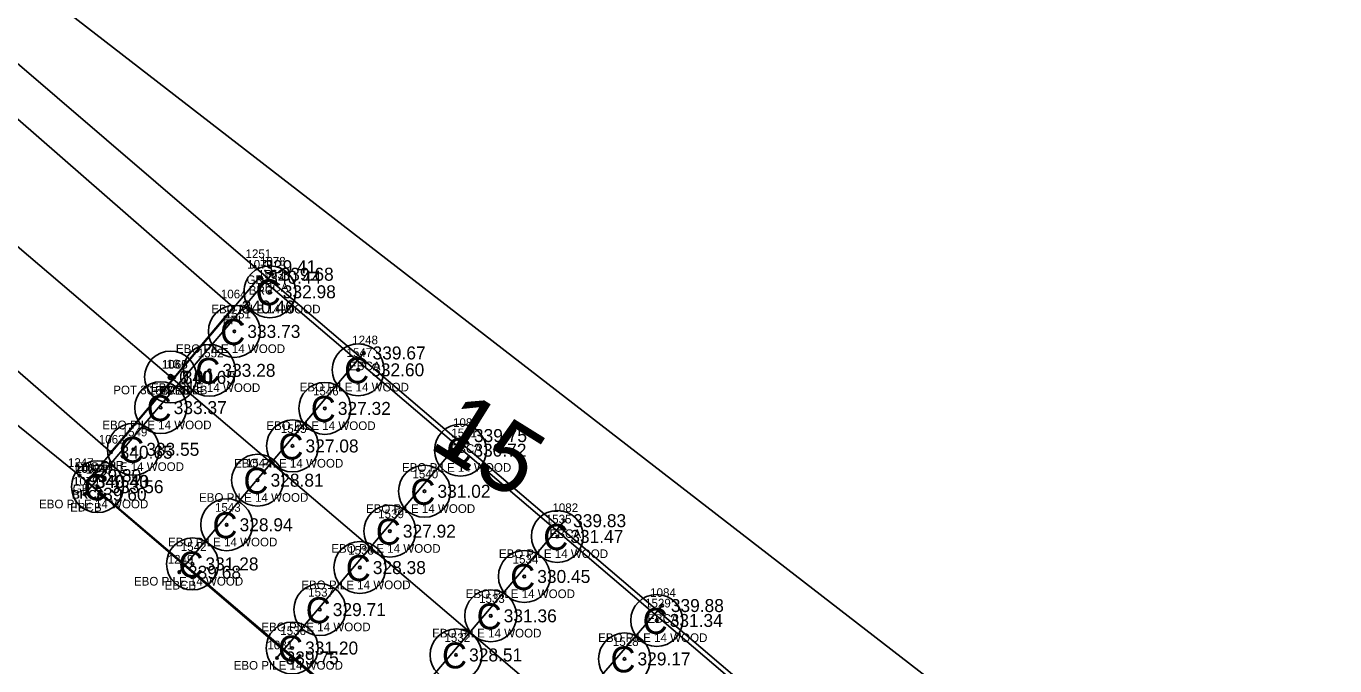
# Model space of a CAD drawing. Extents: x 2006517 to 2008868, y 1001613 to 1004633.
# Drawn here: x 2007680.3 to 2007831.6, y 1003041.7 to 1003115.7 of the extents above; entities that cross this region are included whole.
import ezdxf

# ---------------------------------------------------------------- set-up
doc = ezdxf.new("R2010")
doc.units = 0
for name, color, linetype in [('RD_EX_Bridge', 7, 'Continuous'), ('RD_EX_Bridge_txCode', 7, 'Continuous'), ('RD_EX_GuardRail', 7, 'Continuous'), ('RD_EX_GuardRail_txCode', 7, 'Continuous'), ('RD_EX_Road', 7, 'Continuous'), ('RD_EX_Road_txCode', 7, 'Continuous'), ('RD_EX_TX_Bridge_ELEV', 7, 'Continuous'), ('RD_EX_TX_GuardRail_ELEV', 7, 'Continuous'), ('RD_EX_TX_Road_ELEV', 7, 'Continuous'), ('RD_EX_VEG', 7, 'Continuous'), ('RD_HC_Cl', 7, 'Continuous'), ('RD_HC_Data', 7, 'Continuous'), ('RD_HC_Survey_ELEV', 7, 'Continuous'), ('RD_HC_TX_Sta50', 7, 'Continuous'), ('RD_HC_txCode', 7, 'Continuous'), ('RD_SMD_Locator', 7, 'Continuous')]:
    doc.layers.add(name, color=color, linetype=linetype)

msp = doc.modelspace()

# ---------------------------------------------------------------- linework, layer by layer
at = {"layer": 'RD_EX_Bridge'}
for p, q in [((2007708.71, 1003087), (2007687.08, 1003061.57)), ((2007719.34, 1003077.9), (2007698, 1003052.55)), ((2007731.06, 1003068.35), (2007709.29, 1003042.64)), ((2007742.52, 1003058.51), (2007720.73, 1003032.86)), ((2007753.82, 1003048.7), (2007731.73, 1003023.29))]:
    msp.add_line(p, q, dxfattribs=at)
msp.add_lwpolyline([(2007687.31, 1003063.05), (2007707.28, 1003086.65), (2007780.18, 1003024.5), (2007853.73, 1002962.01), (2007935.92, 1002891.93), (2007915.63, 1002868.5), (2007835.4, 1002936.88), (2007761.92, 1002999.52), (2007687.36, 1003063.04)], dxfattribs=at)
for centre in [(2007708.46, 1003084.97), (2007704.36, 1003080.39), (2007701.48, 1003075.89), (2007718.68, 1003075.95), (2007695.85, 1003071.58), (2007714.82, 1003071.49), (2007692.68, 1003066.76), (2007711.09, 1003067.15), (2007730.5, 1003066.66), (2007688.54, 1003062.44), (2007707.05, 1003063.19), (2007726.34, 1003061.91), (2007703.47, 1003058.04), (2007722.34, 1003057.3), (2007741.7, 1003056.69), (2007699.52, 1003053.51), (2007718.87, 1003053.09), (2007737.88, 1003052.06), (2007714.24, 1003048.23), (2007734, 1003047.51), (2007753.19, 1003046.98), (2007711.04, 1003043.79), (2007729.99, 1003042.99), (2007749.47, 1003042.53)]:
    msp.add_circle(centre, 3, dxfattribs=at)
at = {"layer": 'RD_EX_GuardRail'}
for points in [[(2007643.64, 1003141.95), (2007706.71, 1003087.87), (2007781.32, 1003024.2), (2007854.58, 1002961.97), (2007936.8, 1002891.67), (2008015.14, 1002821.85)], [(2007623.33, 1003114.9), (2007686.46, 1003063.73), (2007759.92, 1003000.81), (2007833.42, 1002938.17), (2007916.12, 1002867.57), (2007997.28, 1002798.14)]]:
    msp.add_lwpolyline(points, dxfattribs=at)
at = {"layer": 'RD_EX_Road'}
for points in [[(2007106.91, 1004392.51), (2007131.76, 1004296.89), (2007157.25, 1004199.89), (2007181.73, 1004104.01), (2007207.15, 1004006.25), (2007232.28, 1003909.68), (2007245.22, 1003859.08), (2007256.72, 1003814.23), (2007281.54, 1003717.98), (2007306.68, 1003621.16), (2007321.26, 1003569.47), (2007336.92, 1003524.18), (2007356.72, 1003477.39), (2007378.16, 1003434.29), (2007403.27, 1003391.08), (2007429.97, 1003350.71), (2007461.24, 1003310.36), (2007493.28, 1003274.3), (2007528.72, 1003239.05), (2007564.79, 1003204.88), (2007704.21, 1003083.21), (2007697.4, 1003075.08)], [(2007086.98, 1004389.35), (2007112.54, 1004291.29), (2007137.93, 1004194.16), (2007162.5, 1004098.34), (2007187.86, 1004000.45), (2007213, 1003903.71), (2007225.92, 1003855.13), (2007237.94, 1003808.26), (2007262.59, 1003712.12), (2007287.86, 1003616), (2007302.39, 1003563.75), (2007318.2, 1003517.19), (2007334.44, 1003476.78), (2007338.05, 1003468.98), (2007341.25, 1003461.96), (2007359.99, 1003424.53), (2007383.83, 1003381.83), (2007412.14, 1003338.08), (2007443.3, 1003296.86), (2007477.49, 1003258.92), (2007512.95, 1003223.51), (2007550.46, 1003188.01), (2007690.1, 1003066.42), (2007697.4, 1003075.08)]]:
    msp.add_lwpolyline(points, dxfattribs=at)
at = {"layer": 'RD_EX_VEG'}
msp.add_lwpolyline([(2007473.93, 1003322.69), (2007503.07, 1003282.99), (2007540.25, 1003252.05), (2007579.27, 1003219.13), (2007642.18, 1003150.48), (2007952.5, 1002910.4), (2008017.59, 1002836.73), (2008047.98, 1002799.05), (2008087.42, 1002767.09), (2008121.48, 1002729.06), (2008151.49, 1002690.42), (2008185.86, 1002650.76), (2008208.76, 1002609.15), (2008254.04, 1002533.01), (2008311.38, 1002450.28), (2008360.35, 1002372.97), (2008409.06, 1002292.02), (2008460.63, 1002215.28), (2008512.48, 1002133.62), (2008564.88, 1002053.16), (2008614.62, 1001980.71), (2008661.43, 1001938.2)], dxfattribs=at)
at = {"layer": 'RD_HC_Cl'}
msp.add_line((2007559.77, 1003192.01), (2007994.36, 1002821.78), dxfattribs=at)
at = {"layer": 'RD_HC_Data'}
for radius in [3, 0.282]:
    msp.add_circle((2007696.99, 1003075.12), radius, dxfattribs=at)
at = {"layer": 'RD_SMD_Locator'}
for centre in [(2007706.71, 1003087.87), (2007707.28, 1003086.65), (2007708.71, 1003087), (2007708.46, 1003084.97), (2007704.21, 1003083.21), (2007704.36, 1003080.39), (2007719.34, 1003077.9), (2007701.48, 1003075.89), (2007718.68, 1003075.95), (2007696.99, 1003075.12), (2007697.4, 1003075.08), (2007697.4, 1003075.08), (2007695.85, 1003071.58), (2007714.82, 1003071.49), (2007731.06, 1003068.35), (2007690.1, 1003066.42), (2007692.68, 1003066.76), (2007711.09, 1003067.15), (2007730.5, 1003066.66), (2007686.46, 1003063.73), (2007707.05, 1003063.19), (2007687.31, 1003063.05), (2007687.36, 1003063.04), (2007688.54, 1003062.44), (2007726.34, 1003061.91), (2007687.08, 1003061.57), (2007703.47, 1003058.04), (2007722.34, 1003057.3), (2007742.52, 1003058.51), (2007741.7, 1003056.69), (2007699.52, 1003053.51), (2007718.87, 1003053.09), (2007698, 1003052.55), (2007737.88, 1003052.06), (2007714.24, 1003048.23), (2007753.82, 1003048.7), (2007734, 1003047.51), (2007753.19, 1003046.98), (2007711.04, 1003043.79), (2007709.29, 1003042.64), (2007729.99, 1003042.99), (2007749.47, 1003042.53)]:
    msp.add_circle(centre, 0.15, dxfattribs=at)

# ---------------------------------------------------------------- texts
at = {"layer": 'RD_EX_Bridge'}
for p in [(2007706.83, 1003083.41), (2007702.73, 1003078.83), (2007699.85, 1003074.33), (2007717.05, 1003074.39), (2007694.22, 1003070.02), (2007713.19, 1003069.93), (2007691.05, 1003065.2), (2007709.46, 1003065.59), (2007728.87, 1003065.09), (2007686.91, 1003060.87), (2007705.41, 1003061.63), (2007724.71, 1003060.35), (2007701.83, 1003056.48), (2007720.71, 1003055.74), (2007740.07, 1003055.13), (2007697.89, 1003051.95), (2007717.24, 1003051.53), (2007736.25, 1003050.5), (2007712.61, 1003046.66), (2007732.37, 1003045.95), (2007751.56, 1003045.42), (2007709.41, 1003042.23), (2007728.36, 1003041.43), (2007747.84, 1003040.97)]:
    msp.add_text('C', height=3, dxfattribs=at).set_placement(p)
at = {"layer": 'RD_EX_Bridge_txCode'}
for s, p in [('1070', (2007705.85, 1003087.65)), ('1078', (2007707.32, 1003088)), ('EBCA', (2007706.99, 1003085)), ('1553', (2007707.11, 1003086.47)), ('BRC', (2007706.03, 1003084.65)), ('EBO PILE 14 WOOD', (2007701.69, 1003082.47)), ('1551', (2007703.3, 1003081.89)), ('EBO PILE 14 WOOD', (2007697.6, 1003077.89)), ('1547', (2007717.33, 1003077.45)), ('1248', (2007717.99, 1003078.9)), ('1552', (2007700.13, 1003077.39)), ('EBCA', (2007717.62, 1003075.9)), ('1550', (2007694.47, 1003073.08)), ('EBO PILE 14 WOOD', (2007694.72, 1003073.39)), ('EBO PILE 14 WOOD', (2007711.91, 1003073.45)), ('1546', (2007713.45, 1003072.99)), ('EBO PILE 14 WOOD', (2007689.09, 1003069.08)), ('EBO PILE 14 WOOD', (2007708.06, 1003068.99)), ('1545', (2007709.74, 1003068.65)), ('1080', (2007729.64, 1003069.35)), ('1549', (2007691.33, 1003068.26)), ('1541', (2007729.44, 1003068.16)), ('EBCA', (2007729.35, 1003066.35)), ('1069', (2007685.9, 1003064.05)), ('EBO PILE 14 WOOD', (2007685.91, 1003064.26)), ('1077', (2007685.98, 1003064.04)), ('1548', (2007687.2, 1003063.94)), ('EBO PILE 14 WOOD', (2007704.32, 1003064.65)), ('1544', (2007705.7, 1003064.69)), ('EBO PILE 14 WOOD', (2007723.74, 1003064.16)), ('1079', (2007685.7, 1003062.57)), ('1540', (2007724.95, 1003063.41)), ('BRCA', (2007685.57, 1003061.05)), ('BRCB', (2007685.64, 1003061.04)), ('EBO PILE 14 WOOD', (2007681.78, 1003059.94)), ('EBCB', (2007685.38, 1003059.57)), ('EBO PILE 14 WOOD', (2007700.28, 1003060.69)), ('1543', (2007702.12, 1003059.54)), ('EBO PILE 14 WOOD', (2007719.57, 1003059.41)), ('1082', (2007741.13, 1003059.51)), ('1539', (2007720.99, 1003058.8)), ('1535', (2007740.36, 1003058.19)), ('EBCA', (2007740.8, 1003056.51)), ('EBO PILE 14 WOOD', (2007696.7, 1003055.54)), ('1542', (2007698.17, 1003055.01)), ('EBO PILE 14 WOOD', (2007715.57, 1003054.8)), ('1249', (2007696.65, 1003053.55)), ('1538', (2007717.52, 1003054.59)), ('EBO PILE 14 WOOD', (2007734.94, 1003054.19)), ('1534', (2007736.53, 1003053.56)), ('EBO PILE 14 WOOD', (2007692.75, 1003051.01)), ('EBCB', (2007696.3, 1003050.55)), ('EBO PILE 14 WOOD', (2007712.1, 1003050.59)), ('1537', (2007712.9, 1003049.73)), ('EBO PILE 14 WOOD', (2007731.11, 1003049.56)), ('1533', (2007732.65, 1003049.01)), ('1084', (2007752.43, 1003049.7)), ('1529', (2007751.84, 1003048.48)), ('EBO PILE 14 WOOD', (2007707.48, 1003045.73)), ('EBCA', (2007752.1, 1003046.7)), ('1536', (2007709.67, 1003045.29)), ('EBO PILE 14 WOOD', (2007727.23, 1003045.01)), ('1532', (2007728.65, 1003044.49)), ('EBO PILE 14 WOOD', (2007746.42, 1003044.48)), ('1081', (2007708.18, 1003043.64)), ('1528', (2007748.12, 1003044.03)), ('EBO PILE 14 WOOD', (2007704.28, 1003041.29))]:
    msp.add_text(s, height=1, dxfattribs=at).set_placement(p)
at = {"layer": 'RD_EX_GuardRail_txCode'}
for s, p in [('1251', (2007705.65, 1003088.87)), ('GR1', (2007705.77, 1003085.87)), ('1247', (2007685.12, 1003064.73)), ('GR', (2007685.68, 1003061.73))]:
    msp.add_text(s, height=1, dxfattribs=at).set_placement(p)
at = {"layer": 'RD_EX_Road_txCode'}
for s, p in [('1064', (2007702.8, 1003084.21)), ('EPL', (2007703.01, 1003081.21)), ('1066', (2007695.97, 1003076.08)), ('1065', (2007696, 1003076.08)), ('EPRB', (2007695.7, 1003073.08)), ('EPLB', (2007695.73, 1003073.08)), ('1063', (2007688.69, 1003067.42)), ('EPR', (2007688.87, 1003064.42))]:
    msp.add_text(s, height=1, dxfattribs=at).set_placement(p)
at = {"layer": 'RD_EX_TX_Bridge_ELEV'}
for s, p in [('339.68', (2007709.71, 1003086.25)), ('340.44', (2007708.28, 1003085.9)), ('332.98', (2007709.96, 1003084.22)), ('333.73', (2007705.86, 1003079.64)), ('339.67', (2007720.34, 1003077.15)), ('333.28', (2007702.98, 1003075.14)), ('332.60', (2007720.18, 1003075.2)), ('333.37', (2007697.35, 1003070.83)), ('327.32', (2007716.32, 1003070.74)), ('327.08', (2007712.59, 1003066.4)), ('339.75', (2007732.06, 1003067.6)), ('333.55', (2007694.18, 1003066.01)), ('330.72', (2007732, 1003065.91)), ('340.43', (2007688.31, 1003062.3)), ('340.40', (2007688.36, 1003062.29)), ('328.81', (2007708.55, 1003062.44)), ('339.60', (2007688.08, 1003060.82)), ('333.56', (2007690.04, 1003061.69)), ('331.02', (2007727.84, 1003061.16)), ('328.94', (2007704.97, 1003057.29)), ('339.83', (2007743.52, 1003057.76)), ('327.92', (2007723.84, 1003056.55)), ('331.47', (2007743.2, 1003055.94)), ('331.28', (2007701.02, 1003052.76)), ('339.68', (2007699, 1003051.8)), ('328.38', (2007720.37, 1003052.34)), ('330.45', (2007739.38, 1003051.31)), ('329.71', (2007715.74, 1003047.48)), ('331.36', (2007735.5, 1003046.76)), ('339.88', (2007754.82, 1003047.95)), ('331.34', (2007754.69, 1003046.23)), ('331.20', (2007712.54, 1003043.04)), ('328.51', (2007731.5, 1003042.24)), ('339.75', (2007710.29, 1003041.89)), ('329.17', (2007750.97, 1003041.78))]:
    msp.add_text(s, height=1.5, dxfattribs=at).set_placement(p)
at = {"layer": 'RD_EX_TX_GuardRail_ELEV'}
for s, p in [('339.41', (2007707.71, 1003087.12)), ('339.80', (2007687.46, 1003062.98))]:
    msp.add_text(s, height=1.5, dxfattribs=at).set_placement(p)
at = {"layer": 'RD_EX_TX_Road_ELEV'}
for s, p in [('340.46', (2007705.21, 1003082.46)), ('340.65', (2007698.4, 1003074.33)), ('340.65', (2007698.4, 1003074.33)), ('340.65', (2007691.1, 1003065.67))]:
    msp.add_text(s, height=1.5, dxfattribs=at).set_placement(p)
at = {"layer": 'RD_HC_Survey_ELEV'}
msp.add_text('0.00', height=1.5, dxfattribs=at).set_placement((2007697.99, 1003074.37))
at = {"layer": 'RD_HC_TX_Sta50'}
msp.add_text('15', height=8, rotation=328.0846, dxfattribs=at).set_placement((2007726.68, 1003067.09))
at = {"layer": 'RD_HC_txCode'}
for s, p in [('13', (2007696.54, 1003076.12)), ('POT 30+43.78 BB', (2007690.36, 1003073.12))]:
    msp.add_text(s, height=1, dxfattribs=at).set_placement(p)

doc.saveas('drawing.dxf')
